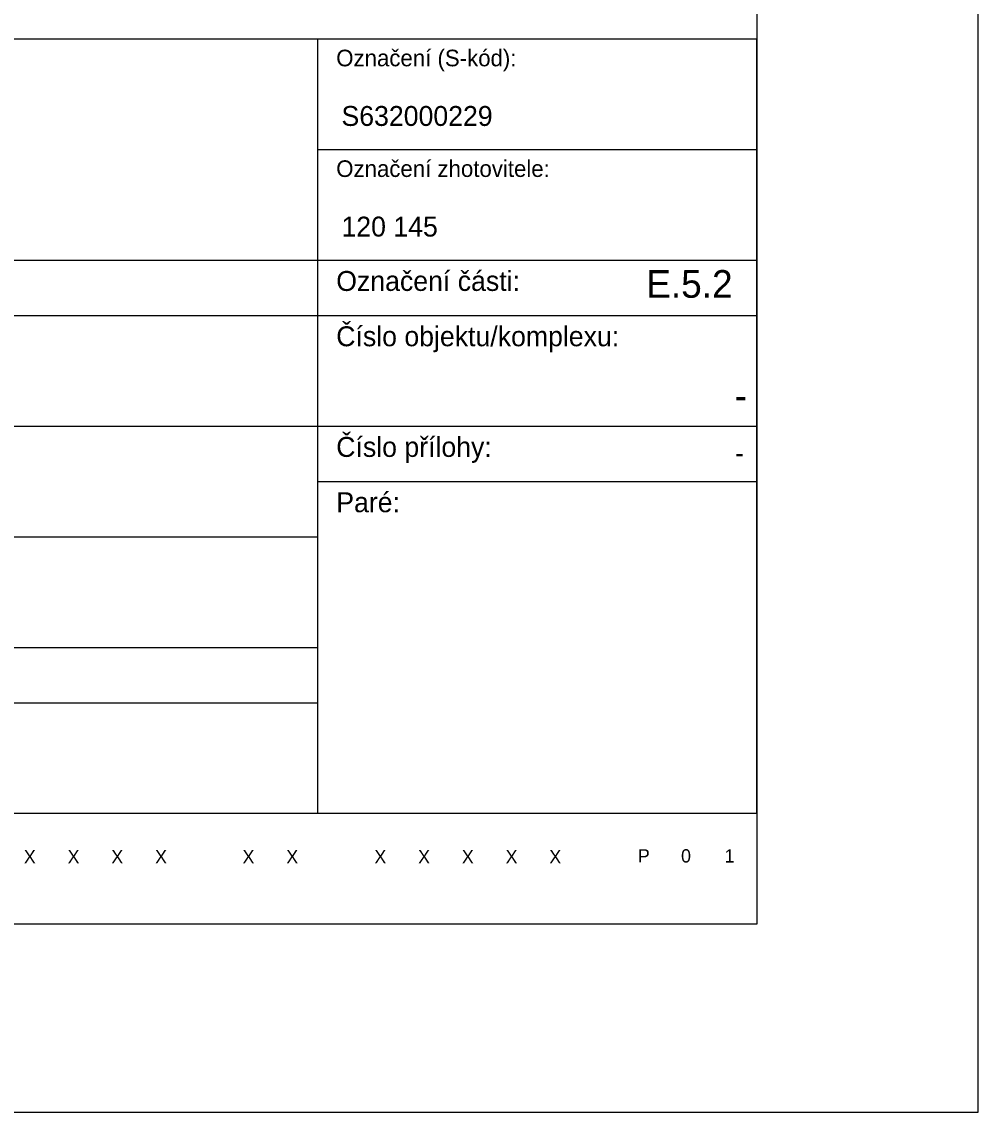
# Model space of a CAD drawing. Extents: x 70 to 280, y -123 to 174.
# Drawn here: x 193.6 to 280, y -123 to -24.5 of the extents above; entities that cross this region are included whole.
import ezdxf

# ---------------------------------------------------------------- set-up
doc = ezdxf.new("R2010")
doc.units = 0
doc.layers.add('SO 11-10-01_popisove_pole', color=7, linetype='Continuous')
doc.layers.add('Vrstva 63', color=7, linetype='Continuous')

msp = doc.modelspace()

# ---------------------------------------------------------------- linework, layer by layer
at = {"layer": 'SO 11-10-01_popisove_pole'}
for p, q in [((220.302, -36.046), (259.952, -36.046)), ((89.952, -46.046), (220.302, -46.046)), ((220.302, -46.046), (259.952, -46.046)), ((89.952, -51.046), (220.302, -51.046)), ((220.302, -51.046), (259.952, -51.046)), ((89.952, -61.046), (220.302, -61.046)), ((220.302, -61.046), (259.952, -61.046)), ((220.302, -66.046), (259.952, -66.046)), ((89.952, -71.046), (220.302, -71.046)), ((89.952, -81.046), (220.302, -81.046)), ((89.952, -86.046), (220.302, -86.046))]:
    msp.add_line(p, q, dxfattribs=at)
for points in [[(279.952, -123.046), (279.952, 173.954), (69.952, 173.954), (69.952, -123.046)], [(89.952, 153.954), (259.952, 153.954), (259.952, -106.046), (89.952, -106.046)], [(89.939, -26.046), (259.939, -26.046), (259.939, -96.046), (89.939, -96.046)], [(259.952, -96.046), (220.302, -96.046), (220.302, -26.046), (259.952, -26.046)]]:
    msp.add_lwpolyline(points, close=True, dxfattribs=at)

# ---------------------------------------------------------------- texts
for s, height, p in [('Označení (S-kód):', 1.5, (221.978, -28.522)), ('S632000229', 1.8, (222.45, -33.91)), ('Označení zhotovitele:', 1.5, (221.978, -38.522)), ('120 145', 1.8, (222.45, -43.91)), ('Označení části:', 1.8, (221.978, -48.822)), ('Číslo objektu/komplexu:', 1.8, (221.978, -53.822)), ('-', 2.5, (257.969, -59.523)), ('Číslo přílohy:', 1.8, (221.978, -63.822)), ('-', 1.8, (257.994, -64.367)), ('Paré:', 1.8, (221.978, -68.822)), ('X', 1.2, (193.767, -100.56)), ('X', 1.2, (197.717, -100.56)), ('X', 1.2, (201.667, -100.56)), ('X', 1.2, (205.617, -100.56)), ('X', 1.2, (213.517, -100.56)), ('X', 1.2, (217.467, -100.56)), ('X', 1.2, (225.424, -100.56)), ('X', 1.2, (229.374, -100.56)), ('X', 1.2, (233.324, -100.56)), ('X', 1.2, (237.274, -100.56)), ('X', 1.2, (241.224, -100.56)), ('P', 1.2, (249.221, -100.479)), ('0', 1.2, (253.121, -100.479)), ('1', 1.2, (257.053, -100.481))]:
    msp.add_text(s, height=height, rotation=360, dxfattribs=at).set_placement(p)
at = {"layer": 'Vrstva 63'}
msp.add_text('E.5.2', height=2.5, dxfattribs=at).set_placement((249.969, -49.441))

doc.saveas('drawing.dxf')
